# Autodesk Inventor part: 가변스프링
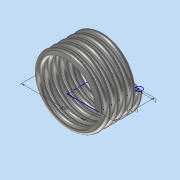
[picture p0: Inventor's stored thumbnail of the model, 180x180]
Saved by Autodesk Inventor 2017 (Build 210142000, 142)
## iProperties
Part Number: 가변스프링
Material: 스테인레스 스틸
Document SubType Name: Modeling
Designer: mrc
Density: 8 g/cm^3
Appearance: 반연마
Mass: 7.62498 g
Surface Area: 19.5771 cm^2
Volume: 0.953123 cm^3
Author: mrc
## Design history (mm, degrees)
sketch "스케치1"
  geometry: L1 (0, -12.7)-(10, -12.7); L2 (10, -12.7)-(10, 0); L3 (10, 0)-(0, 0); L4 (0, 0)-(0, -12.7); C1 r 1 at (10, 0); 1 further point
  constraints: 8 end point, 2 coincident, 2 parallel, 1 centre point, 1 horizontal, 1 perpendicular
  dimensions: "d0" = 12.7 distance between parallel lines of L3 L1 (derived); "d1" = 20 diameter of L2 L4; "d2" = 2 diameter of C1
feature "코일2" sketch "스케치1" pitch "d14" = 10; turns "d16" = 5; dims "d15" = 12.7 (= d0), "d17" = 0, angle "d18" = 90 deg, angle "d19" = 90 deg, "d20" = 0, "d21" = 0
sketch "스케치3"
  geometry: L1 (-20, -12.7)-(20, -12.7); L2 (20, -12.7)-(20, 0); L3 (20, 0)-(-20, 0); L4 (-20, 0)-(-20, -12.7); L5 (0, 0)-(0, -12.7) reference; 2 further points
  constraints: 8 end point, 2 midpoint, 2 parallel, 1 coincident, 1 horizontal, 1 perpendicular
  dimensions: "d22" = 40 distance of L1.start L1.end
extrude "돌출2" sketch "스케치3" stored distance "d23" = 0; taper "d24" = 0 deg
node "솔리드2"
